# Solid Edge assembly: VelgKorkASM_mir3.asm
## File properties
Author: KULL
Template: Iso Metric Assembly.asm
Last saved by: KULL
Revision: 2
Application: Solid Edge
Username: KULL
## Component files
Velg2_mir3.par
VeljekorkASM_mir3.asm
Rehv1_mir3.par
VelgKorkASM.asm
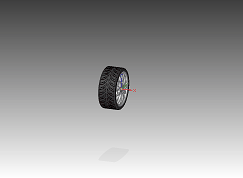
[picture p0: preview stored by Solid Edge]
